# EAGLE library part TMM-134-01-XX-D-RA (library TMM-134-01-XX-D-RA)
2MM RIGHT ANGLE TERMINAL STRIP ASSEMBLY.
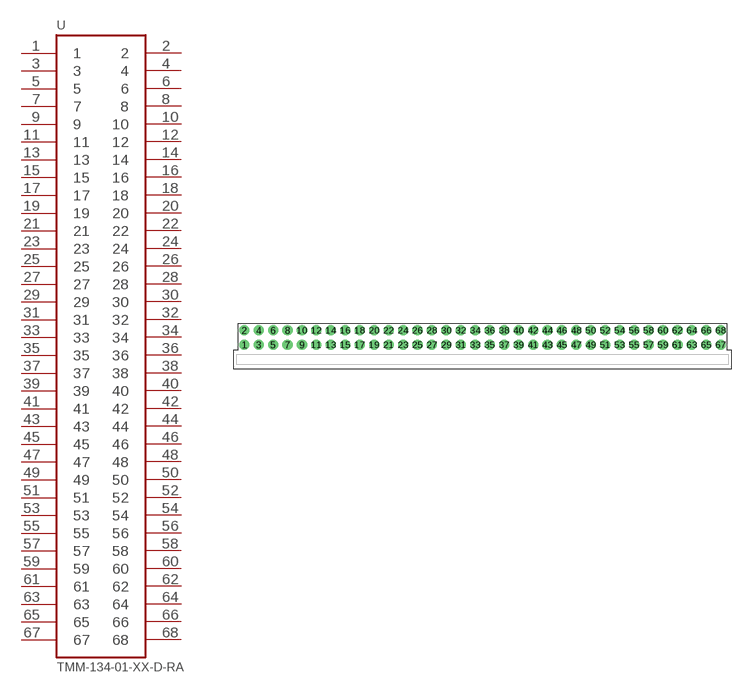
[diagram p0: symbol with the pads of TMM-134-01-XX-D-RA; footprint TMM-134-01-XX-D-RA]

Designator prefix -

## TMM-134-01-XX-D-RA  [TMM-134-01-XX-D-RA]
1  1
2  2
3  3
4  4
5  5
6  6
7  7
8  8
9  9
10  10
11  11
12  12
13  13
14  14
15  15
16  16
17  17
18  18
19  19
20  20
21  21
22  22
23  23
24  24
25  25
26  26
27  27
28  28
29  29
30  30
31  31
32  32
33  33
34  34
35  35
36  36
37  37
38  38
39  39
40  40
41  41
42  42
43  43
44  44
45  45
46  46
47  47
48  48
49  49
50  50
51  51
52  52
53  53
54  54
55  55
56  56
57  57
58  58
59  59
60  60
61  61
62  62
63  63
64  64
65  65
66  66
67  67
68  68

## Footprint TMM-134-01-XX-D-RA (pad centres in mm)
2MM RIGHT ANGLE TERMINAL STRIP ASSEMBLY.
drill 0.889 pad 1.321 round: 1 -33,0; 2 -33,2; 3 -31,0; 4 -31,2; 5 -29,0; 6 -29,2; 7 -27,0; 8 -27,2; 9 -25,0; 10 -25,2; 11 -23,0; 12 -23,2; 13 -21,0; 14 -21,2; 15 -19,0; 16 -19,2; 17 -17,0; 18 -17,2; 19 -15,0; 20 -15,2; 21 -13,0; 22 -13,2; 23 -11,0; 24 -11,2; 25 -9,0; 26 -9,2; 27 -7,0; 28 -7,2; 29 -5,0; 30 -5,2; 31 -3,0; 32 -3,2; 33 -1,0; 34 -1,2; 35 1,0; 36 1,2; 37 3,0; 38 3,2; 39 5,0; 40 5,2; 41 7,0; 42 7,2; 43 9,0; 44 9,2; 45 11,0; 46 11,2; 47 13,0; 48 13,2; 49 15,0; 50 15,2; 51 17,0; 52 17,2; 53 19,0; 54 19,2; 55 21,0; 56 21,2; 57 23,0; 58 23,2; 59 25,0; 60 25,2; 61 27,0; 62 27,2; 63 29,0; 64 29,2; 65 31,0; 66 31,2; 67 33,0; 68 33,2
